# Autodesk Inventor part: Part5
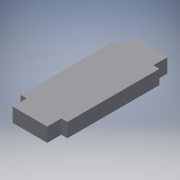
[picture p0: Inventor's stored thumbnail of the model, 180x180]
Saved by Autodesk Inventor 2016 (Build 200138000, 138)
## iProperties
Created: 2017-06
Part Number: Part5
Material: Generic
Document SubType Name: Modeling
Designer: laboratorioesan
Density: 1 g/cm^3
Appearance: Default
Author: laboratorioesan
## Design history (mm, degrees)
sketch "Sketch1"
  geometry: L1 (0, 0)-(-7, 0) reference; L2 (0, 0)-(0, 3) reference; L3 (-7, 3)-(0, 3) reference; L4 (-7, 0)-(-7, 3) reference; L5 (1.5, 32.825)-(1.5, -7.175) reference; L6 (4.5, 25.65)-(4.5, 22.65) reference; L7 (4.5, 25.65)-(1.5, 25.65) reference; L8 (1.5, 22.65)-(1.5, 25.65) reference; L9 (4.5, 22.65)-(1.5, 22.65) reference; L10 (1.5, 3)-(-8.5, 3); L11 (-8.5, 3)-(-8.5, 22.65); L12 (-8.5, 22.65)-(1.5, 22.65); L13 (1.5, 22.65)-(1.5, 3); L14 (-7.2, 3)-(-7.2, 0); L15 (-7.2, 0)-(0.2, 0); L16 (0.2, 0)-(0.2, 3); L17 (-7.2, 22.65)-(-7.2, 25.65); L18 (-7.2, 25.65)-(0.2, 25.65); L19 (0.2, 25.65)-(0.2, 22.65); L20 (4.5, 0)-(1.5, 0) reference; L21 (4.5, 3)-(1.5, 3) reference
  constraints: 20 end point, 10 point on line, 4 horizontal alignment, 3 perpendicular, 2 parallel, 2 vertical alignment, 1 horizontal, 1 vertical
  dimensions: "d0" = 1.5 distance of L3.start L10.end; "d1" = 0.2 distance of L1.end L14.end; "d2" = 0.2 distance of L1.start L15.end; "d3" = 19.65 distance of L10.end L11.end
extrude "Extrusion1" new body sketch "Sketch1" distance "d4" = 3; taper "d5" = 0 deg
body "Solid1"
node "Reference1"
node "Reference2"
node "Reference3"
node "Reference4"
node "Reference5"
